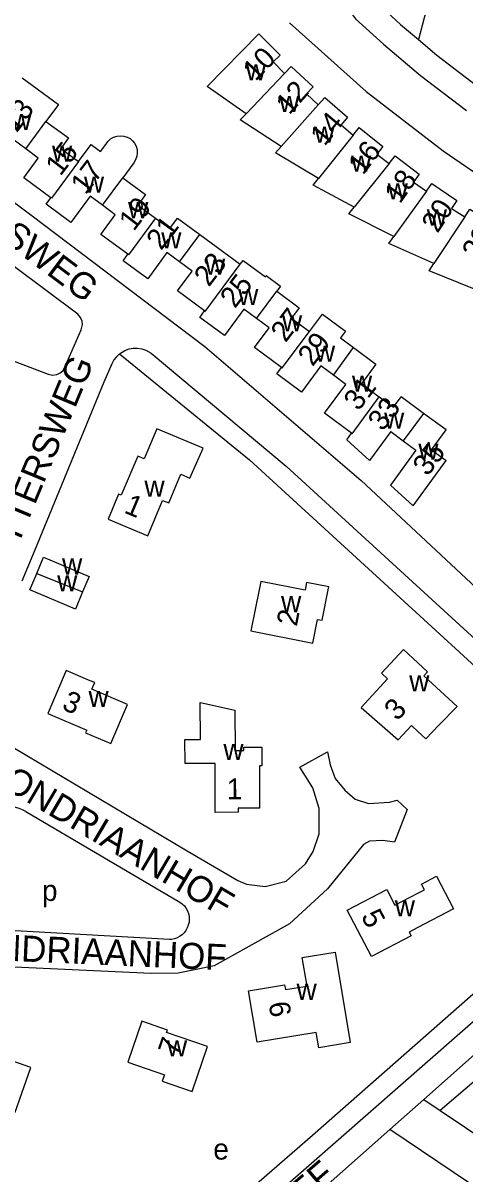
# Model space of a CAD drawing. Extents: x 162804 to 165059, y 381530 to 382901.
# Drawn here: x 163924.4 to 164009, y 381888 to 382108.7 of the extents above; entities that cross this region are included whole.
import ezdxf

# ---------------------------------------------------------------- set-up
doc = ezdxf.new("R2010")
doc.units = 0
for name, color, linetype in [('BLT_Basislijn', 7, 'Continuous'), ('BLT_Bebouwing', 7, 'Continuous'), ('BLT_Centroide', 7, 'Continuous'), ('BLT_Huisnummer', 7, 'Continuous'), ('BLT_Huisnummer_ tussenligend', 7, 'Continuous'), ('BLT_Onderverdeling_panden', 7, 'Continuous'), ('BLT_Straatnaam', 7, 'Continuous'), ('BLT_Vlakafsluiter', 7, 'Continuous')]:
    doc.layers.add(name, color=color, linetype=linetype)

msp = doc.modelspace()

# ---------------------------------------------------------------- linework, layer by layer
at = {"layer": 'BLT_Basislijn'}
for p, q in [((164002.37, 382114.16), (164000.11, 382105.51)), ((164004.84, 382084.13), (164015.86, 382076.6)), ((163925.88, 382071.87), (163959.2, 382046.68)), ((163959.2, 382046.68), (163989.12, 382020.94)), ((163989.12, 382020.94), (164018.83, 381993.23)), ((163924.89, 381957.53), (163954.43, 381940.14)), ((163952.4, 381932.95), (163917.61, 381934.91)), ((164001.14, 381902.31), (164013.17, 381912.96)), ((164001.14, 381902.31), (164004.28, 381900.2)), ((164004.28, 381900.2), (164087.97, 381843.76)), ((163960.96, 381866.73), (163994.65, 381896.56))]:
    msp.add_line(p, q, dxfattribs=at)
for points in [[(163915.4, 382046.58), (163929.16, 382041.32), (163929.98, 382041.14), (163930.83, 382041.26), (163931.5, 382041.58), (163931.96, 382041.99), (163932.39, 382042.66), (163935.5, 382049.87), (163935.74, 382050.87), (163935.68, 382051.49), (163935.36, 382052.23), (163934.83, 382052.85), (163850.87, 382115.63), (163850.01, 382116.38), (163849.32, 382117.21), (163848.78, 382118.13), (163848.37, 382119.03), (163848.07, 382120.09), (163847.96, 382120.7), (163847.96, 382121.67)], [(163859.34, 382121.57), (163925.88, 382071.87)], [(163986.54, 382118.01), (163986.11, 382116.26), (163985.96, 382115.24), (163985.96, 382114.35), (163986.09, 382113.39), (163986.43, 382112.19), (163986.73, 382111.49), (163986.92, 382111.1), (163987.32, 382110.47), (163987.66, 382109.97), (163988.09, 382109.47), (163993.41, 382104.62), (164000.55, 382098.6), (164009.36, 382091.88)], [(163986.54, 382118.01), (163991.7, 382112.95), (163996.71, 382108.38), (164000.11, 382105.51)], [(163975.44, 382108.72), (163990.12, 382095.52), (164004.84, 382084.13)], [(164000.11, 382105.51), (164003.68, 382102.5), (164012.36, 382095.88), (164018.33, 382091.47), (164021.16, 382089.69), (164033.68, 382081.99)], [(163942.85, 382045.24), (163943.88, 382045.91), (163944.68, 382046.18), (163945.43, 382046.3), (163946.28, 382046.34), (163947.14, 382046.2), (163947.91, 382045.97), (163948.94, 382045.37), (163974.77, 382023.71), (164048.11, 381956.56), (164048.67, 381955.87), (164048.35, 381950.3), (163846.25, 381773.14), (163842.47, 381770.18), (163838.71, 381770.12), (163836.54, 381770.96)], [(163942.85, 382045.24), (163967.78, 382024.92), (164044.46, 381954.63), (164045.58, 381953.26), (163979.85, 381895.4), (163836.54, 381770.96)], [(163942.85, 382045.24), (163942.18, 382044.58), (163941.78, 382044.07), (163941.38, 382043.35), (163939.84, 382039.83), (163926.54, 382007.48), (163924.12, 382001.64)], [(163915.57, 381973.87), (163955.79, 381949.95), (163965.52, 381944.27), (163967.16, 381943.58), (163970.73, 381943.15), (163974.77, 381944.18), (163978.48, 381947.51), (163979.97, 381949.82), (163981.08, 381953.26), (163981.11, 381958.07), (163979.87, 381962.08), (163977.42, 381966), (163982.67, 381968.93), (163983.2, 381966.45), (163984.2, 381963.87), (163986.02, 381961.6), (163988.01, 381959.87), (163990.53, 381959.05), (163994.55, 381959.28), (163996.05, 381959.68), (163997.96, 381957.88), (163995.55, 381951.64), (163993.3, 381951.95), (163990.73, 381951.83), (163989.6, 381951.19), (163982.67, 381942.69), (163975.44, 381935.97), (163960.95, 381927.94), (163954.1, 381926.51), (163948.91, 381926.43), (163910.28, 381928.23)], [(163924.89, 381957.53), (163924.28, 381957.85), (163923.63, 381958.09), (163922.97, 381958.26), (163922.29, 381958.35), (163921.6, 381958.37), (163920.91, 381958.3), (163920.24, 381958.15), (163919.59, 381957.93), (163918.97, 381957.63), (163918.39, 381957.26), (163917.85, 381956.83), (163917.37, 381956.34), (163916.95, 381955.79), (163916.64, 381955.29)], [(164127.67, 381897.27), (164076.18, 381932.74), (164061.65, 381943.36), (164056.35, 381941.19), (164045.96, 381934.74), (164032.59, 381924.37), (164004.28, 381900.2)], [(163954.43, 381940.14), (163954.88, 381939.8), (163955.27, 381939.4), (163955.6, 381938.95), (163955.87, 381938.46), (163956.06, 381937.93), (163956.17, 381937.38), (163956.2, 381936.82), (163956.16, 381936.27), (163956.03, 381935.72), (163955.83, 381935.2), (163955.56, 381934.71), (163955.22, 381934.27), (163954.82, 381933.88), (163954.37, 381933.55), (163953.88, 381933.29), (163953.35, 381933.1), (163952.8, 381932.99), (163952.4, 381932.95)], [(164022.24, 381877.95), (163994.65, 381896.56)]]:
    msp.add_lwpolyline(points, dxfattribs=at)
at = {"layer": 'BLT_Bebouwing'}
for p, q in [((163928.75, 382089.79), (163933.06, 382086.62)), ((163924.87, 382084.54), (163922.46, 382086.32)), ((163933.06, 382086.62), (163931.58, 382084.61)), ((163927.28, 382082.76), (163924.87, 382084.54)), ((163931.58, 382084.61), (163935.01, 382082.09)), ((163924.51, 382078.99), (163927.28, 382082.76)), ((163943.47, 382078.97), (163947.82, 382075.77)), ((163939.59, 382073.72), (163937.2, 382075.48)), ((163947.82, 382075.77), (163946.34, 382073.76)), ((163942.02, 382071.92), (163939.59, 382073.72)), ((163946.34, 382073.76), (163949.74, 382071.25)), ((163939.24, 382068.14), (163942.02, 382071.92)), ((163949.74, 382071.25), (163952.46, 382069.26)), ((163952.46, 382069.26), (163953.94, 382071.27)), ((163953.94, 382071.27), (163958.25, 382068.1)), ((163958.25, 382068.1), (163965.97, 382062.41)), ((163954.34, 382062.86), (163951.93, 382064.64)), ((163953.98, 382057.29), (163956.75, 382061.08)), ((163956.75, 382061.08), (163954.34, 382062.86)), ((163972.99, 382057.25), (163977.3, 382054.08)), ((163969.08, 382052.01), (163966.67, 382053.79)), ((163977.3, 382054.08), (163975.82, 382052.07)), ((163968.71, 382046.45), (163971.49, 382050.23)), ((163971.49, 382050.23), (163969.08, 382052.01)), ((163975.82, 382052.07), (163979.25, 382049.55)), ((163987.69, 382046.45), (163991.98, 382043.29)), ((163991.98, 382043.29), (163989.2, 382039.52)), ((163983.82, 382041.16), (163981.4, 382042.94)), ((163986.22, 382039.38), (163983.82, 382041.16)), ((163989.2, 382039.52), (163992.63, 382036.99)), ((163992.63, 382036.99), (163995.33, 382035)), ((163995.33, 382035), (163996.81, 382037.01)), ((164001.12, 382033.83), (163996.81, 382037.01)), ((164005.43, 382030.66), (164001.12, 382033.83)), ((163994.81, 382030.35), (163997.23, 382028.57)), ((164002.63, 382026.86), (164005.43, 382030.66)), ((163986.42, 382028.78), (163987.32, 382030.02)), ((163997.23, 382028.57), (163999.65, 382026.8)), ((164002.63, 382026.86), (164005.46, 382024.77)), ((163999.12, 382016.13), (164005.46, 382024.77))]:
    msp.add_line(p, q, dxfattribs=at)
for points in [[(163967.1, 382091.28), (163959.63, 382096.49), (163969.55, 382106.57), (163973.6, 382102.49), (163972.28, 382101.2), (163974.46, 382099.01)], [(163974.46, 382099.01), (163975.73, 382100.35), (163979.95, 382096.42), (163978.66, 382095.08), (163980.92, 382092.96)], [(163924.2, 382098.16), (163931.16, 382093.04), (163928.75, 382089.79)], [(163980.92, 382092.96), (163982.16, 382094.35), (163986.51, 382090.58), (163985.3, 382089.15), (163987.65, 382087.15)], [(163973.81, 382085.02), (163965.96, 382090.09), (163967.1, 382091.28)], [(163987.65, 382087.15), (163988.8, 382088.6), (163993.3, 382085.01), (163992.14, 382083.54), (163994.53, 382081.74)], [(163935.01, 382082.09), (163937.43, 382085.35), (163939.21, 382084.03), (163940.24, 382085.4), (163940.6, 382085.94), (163941.14, 382086.43), (163941.71, 382086.76), (163942.39, 382086.99), (163943.05, 382087.05), (163943.68, 382086.98), (163944.34, 382086.77), (163944.86, 382086.5), (163945.33, 382086.08), (163945.72, 382085.63), (163946.02, 382085.04), (163946.2, 382084.42), (163946.25, 382083.77), (163946.18, 382083.14), (163945.93, 382082.44), (163945.58, 382081.87), (163943.47, 382078.97)], [(163980.98, 382078.83), (163972.72, 382083.8), (163973.81, 382085.02)], [(163994.53, 382081.74), (163995.68, 382083.17), (164000.29, 382079.71), (163999.2, 382078.17), (164001.68, 382076.45)], [(163929.68, 382075.17), (163924.51, 382078.99)], [(163987.8, 382073.39), (163979.96, 382077.55), (163980.98, 382078.83)], [(164001.68, 382076.45), (164002.71, 382077.87), (164007.5, 382074.66), (164006.46, 382073.09), (164009.02, 382071.5)], [(163937.2, 382075.48), (163933.51, 382070.45), (163928.78, 382073.93)], [(163928.78, 382073.93), (163929.68, 382075.17)], [(163995.41, 382067.75), (163986.77, 382072.11), (163987.8, 382073.39)], [(164009.02, 382071.5), (164009.99, 382072.97), (164014.89, 382069.9), (164013.86, 382068.27), (164016.45, 382066.68)], [(163944.42, 382064.33), (163939.24, 382068.14)], [(164003.06, 382062.54), (163994.45, 382066.42), (163995.41, 382067.75)], [(163951.93, 382064.64), (163948.24, 382059.6), (163943.52, 382063.08)], [(163943.52, 382063.08), (163944.42, 382064.33)], [(163965.97, 382062.41), (163966.52, 382063.16), (163970.79, 382060.02)], [(164010.9, 382057.62), (164002.16, 382061.18), (164003.06, 382062.54)], [(163970.79, 382060.02), (163970.96, 382060.24), (163973.7, 382058.23), (163972.99, 382057.25)], [(163959.15, 382053.48), (163953.98, 382057.29)], [(163966.67, 382053.79), (163962.98, 382048.76), (163958.25, 382052.24)], [(163958.25, 382052.24), (163959.15, 382053.48)], [(163979.25, 382049.55), (163981.72, 382052.84)], [(163981.72, 382052.84), (163986.15, 382049.59), (163985.18, 382048.29), (163987.69, 382046.44)], [(163973.89, 382042.63), (163968.71, 382046.45)], [(163981.4, 382042.94), (163977.71, 382037.91), (163972.99, 382041.39)], [(163972.99, 382041.39), (163973.89, 382042.63)], [(163987.32, 382030.02), (163982.15, 382033.84), (163986.22, 382039.38)], [(163949.98, 382030.84), (163947.58, 382025.12)], [(163948.25, 382010.35), (163951.1, 382017.15), (163952.29, 382016.65), (163952.67, 382017.56), (163954.6, 382022.17), (163956.35, 382021.4), (163958.9, 382027.16), (163949.98, 382030.84)], [(163994.81, 382030.35), (163990.75, 382024.82), (163986.42, 382028.78)], [(163947.58, 382025.12), (163946.34, 382025.64), (163943.19, 382018.12), (163942.65, 382018.34), (163940.64, 382013.54), (163948.25, 382010.35)], [(163999.65, 382026.8), (163994.75, 382020.1), (163999.12, 382016.13)], [(163926.97, 382003.14), (163928.25, 382006.27), (163937.03, 382002.59), (163935.78, 381999.61)], [(163925.68, 382000), (163926.97, 382003.14)], [(163978.42, 381999.95), (163969.94, 382001.63), (163969.61, 382000), (163968.04, 381992.16), (163979.86, 381989.81), (163980.76, 381994.34), (163981.65, 381994.16), (163982.84, 382000), (163982.95, 382000.55), (163978.7, 382001.4), (163978.42, 381999.95)], [(163935.78, 381999.61), (163934.42, 381996.33), (163925.68, 382000)], [(164004.06, 381974.04), (164007.56, 381977.61), (164001.18, 381983.51), (164001.89, 381984.27), (164000, 381986.02), (163997.27, 381988.55), (163993.06, 381984), (163994.21, 381982.94), (163989.14, 381977.46), (163996.24, 381971.25), (163998.79, 381974), (164000, 381972.88), (164001.54, 381971.46), (164004.06, 381974.04)], [(163941.15, 381970.53), (163944.39, 381978.05), (163937.57, 381980.99), (163938.1, 381982.23), (163937.25, 381982.59), (163932.65, 381984.57), (163929.09, 381976.3), (163936.55, 381973.08), (163936.34, 381972.6), (163941.15, 381970.53)], [(163960.09, 381978.02), (163964.97, 381976.95), (163965.01, 381969.19), (163966.65, 381969.2), (163966.65, 381969.84), (163970.09, 381969.85), (163970.11, 381966.28), (163969.66, 381966.28), (163969.7, 381958.15), (163965.59, 381958.13), (163965.59, 381957.36), (163961.19, 381957.34), (163961.15, 381966.72), (163955.41, 381966.7), (163955.38, 381971.3), (163958.34, 381971.31), (163958.3, 381978.42), (163960.09, 381978.02)], [(164000.01, 381941.83), (164001.29, 381942.51), (164000.71, 381943.61), (164003.58, 381945.11), (164006.84, 381938.84), (164000, 381935.25), (163998.34, 381934.38), (163998.71, 381933.68), (163991.12, 381929.7), (163986.47, 381938.58), (163994.05, 381942.55), (163995.63, 381939.54), (164000.01, 381941.83)], [(163981.05, 381912.23), (163980.56, 381915.18), (163969.2, 381913.28), (163967.56, 381923.12), (163974.46, 381924.27), (163974.62, 381923.36), (163978.79, 381924.06), (163977.87, 381929.53), (163984.15, 381930.58), (163987.05, 381913.23), (163981.05, 381912.23)], [(163959.7, 381912.49), (163951.87, 381915.17), (163952.03, 381915.61), (163947.12, 381917.29), (163944.44, 381909.46), (163951.47, 381907.06), (163951.04, 381905.79), (163956.74, 381903.84), (163959.7, 381912.49)], [(163925.88, 381908.41), (163918, 381911.18), (163918.2, 381911.75), (163913.34, 381913.47), (163910.55, 381905.56), (163917.7, 381903.04), (163917.27, 381901.83), (163922.86, 381899.86), (163925.88, 381908.41)]]:
    msp.add_lwpolyline(points, dxfattribs=at)
at = {"layer": 'BLT_Onderverdeling_panden'}
for p, q in [((163974.46, 382099.01), (163967.1, 382091.28)), ((163980.92, 382092.96), (163973.81, 382085.02)), ((163924.87, 382084.54), (163928.75, 382089.79)), ((163987.65, 382087.15), (163980.98, 382078.83)), ((163994.53, 382081.74), (163987.8, 382073.39)), ((163939.59, 382073.72), (163943.47, 382078.97)), ((164001.68, 382076.45), (163995.41, 382067.75)), ((164009.02, 382071.5), (164003.06, 382062.54)), ((163954.34, 382062.86), (163958.25, 382068.1)), ((163969.08, 382052.01), (163972.99, 382057.25)), ((163983.82, 382041.16), (163987.69, 382046.45)), ((164001.12, 382033.83), (163997.23, 382028.57)), ((163926.97, 382003.14), (163935.78, 381999.61))]:
    msp.add_line(p, q, dxfattribs=at)
for points in [[(163935.01, 382082.09), (163929.8, 382075.08), (163929.68, 382075.17)], [(163949.74, 382071.25), (163944.54, 382064.24), (163944.42, 382064.33)], [(163959.15, 382053.48), (163959.27, 382053.39), (163965.97, 382062.41)], [(163973.89, 382042.63), (163974.01, 382042.55), (163979.25, 382049.55)], [(163987.32, 382030.02), (163987.44, 382029.93), (163992.63, 382036.99)]]:
    msp.add_lwpolyline(points, dxfattribs=at)
at = {"layer": 'BLT_Vlakafsluiter'}
msp.add_line((163994.65, 381896.56), (164001.14, 381902.31), dxfattribs=at)

# ---------------------------------------------------------------- texts
at = {"layer": 'BLT_Centroide'}
for s, p in [('w', (163967.05, 382097.67)), ('w', (163973.44, 382091.59)), ('w', (163922.1, 382088.12)), ('w', (163980.19, 382085.72)), ('w', (163929.91, 382082.08)), ('w', (163987.23, 382080.17)), ('w', (163936.03, 382076.16)), ('w', (163994.23, 382074.86)), ('w', (163944.48, 382071.25)), ('w', (164001.73, 382069.84)), ('w', (163950.84, 382065.44)), ('w', (163959.23, 382060.41)), ('w', (163965.58, 382054.59)), ('w', (163973.98, 382049.55)), ('w', (163980.3, 382043.75)), ('w', (163987.39, 382038)), ('w', (163993.55, 382030.91)), ('w', (164000.11, 382024.97)), ('w', (163947.62, 382017.84)), ('w', (163931.84, 382002.94)), ('w', (163930.9, 381999.72)), ('w', (163973.81, 381995.72)), ('w', (163998.36, 381980.53)), ('w', (163936.9, 381977.56)), ('w', (163962.75, 381967.39)), ('p', (163927.99, 381940.37)), ('w', (163995.6, 381937.41)), ('w', (163976.77, 381921.41)), ('w', (163951.93, 381910.56)), ('e', (163960.82, 381890.79))]:
    msp.add_text(s, height=4, dxfattribs=at).set_placement(p)
at = {"layer": 'BLT_Huisnummer'}
for s, rotation, p in [('10', 46.0392, (163968.92, 382097.36)), ('14', 50.4412, (163982.13, 382084.91)), ('15', 52.5793, (163931.51, 382079.15)), ('18', 54.8374, (163996.57, 382073.85)), ('19', 52.588, (163945.57, 382068.59)), ('22', 59.238, (164011.63, 382063.01)), ('23', 52.6016, (163959.97, 382057.93)), ('27', 52.5967, (163974.67, 382047.26)), ('31', 52.6016, (163988.65, 382034.13)), ('35', 52.5967, (164001.88, 382021.62)), ('1', 337.262, (163943.53, 382014.86)), ('2', 78.7558, (163976.81, 381992.86)), ('3', 336.6829, (163931.6, 381977.19)), ('3', 45.5726, (163996.03, 381974.73)), ('1', 0.2995, (163963.39, 381959.85)), ('5', 297.6337, (163989.05, 381937.46)), ('6', 279.4793, (163971.39, 381920.78)), ('7', 71.1194, (163953.91, 381910.51))]:
    msp.add_text(s, height=4, rotation=rotation, dxfattribs=at).set_placement(p)
at = {"layer": 'BLT_Huisnummer_ tussenligend'}
for s, rotation, p in [('12', 48.2396, (163975.38, 382090.91)), ('13', 52.5963, (163923.06, 382087.4)), ('16', 52.6382, (163989.5, 382079.37)), ('17', 52.5963, (163936.34, 382075.59)), ('20', 57.0409, (164003.79, 382068.22)), ('21', 52.5963, (163950.82, 382064.94)), ('25', 52.5963, (163964.96, 382053.8)), ('29', 52.5963, (163979.85, 382042.66)), ('33', 52.5963, (163993.28, 382030.22))]:
    msp.add_text(s, height=4, rotation=rotation, dxfattribs=at).set_placement(p)
at = {"layer": 'BLT_Straatnaam'}
for s, rotation, p in [('RIK WOUTERSWEG', 323.1711, (163885.82, 382092.71)), ('JAN SLUYTERSWEG', 67.4526, (163912.79, 381982.83)), ('MONDRIAANHOF', 329.4597, (163915.42, 381965.01)), ('MONDRIAANHOF', 357.4597, (163908.33, 381929.48)), ('PUTTENSEDREEF', 40.7413, (163940.37, 381849.14))]:
    msp.add_text(s, height=5, rotation=rotation, dxfattribs=at).set_placement(p)

doc.saveas('drawing.dxf')
